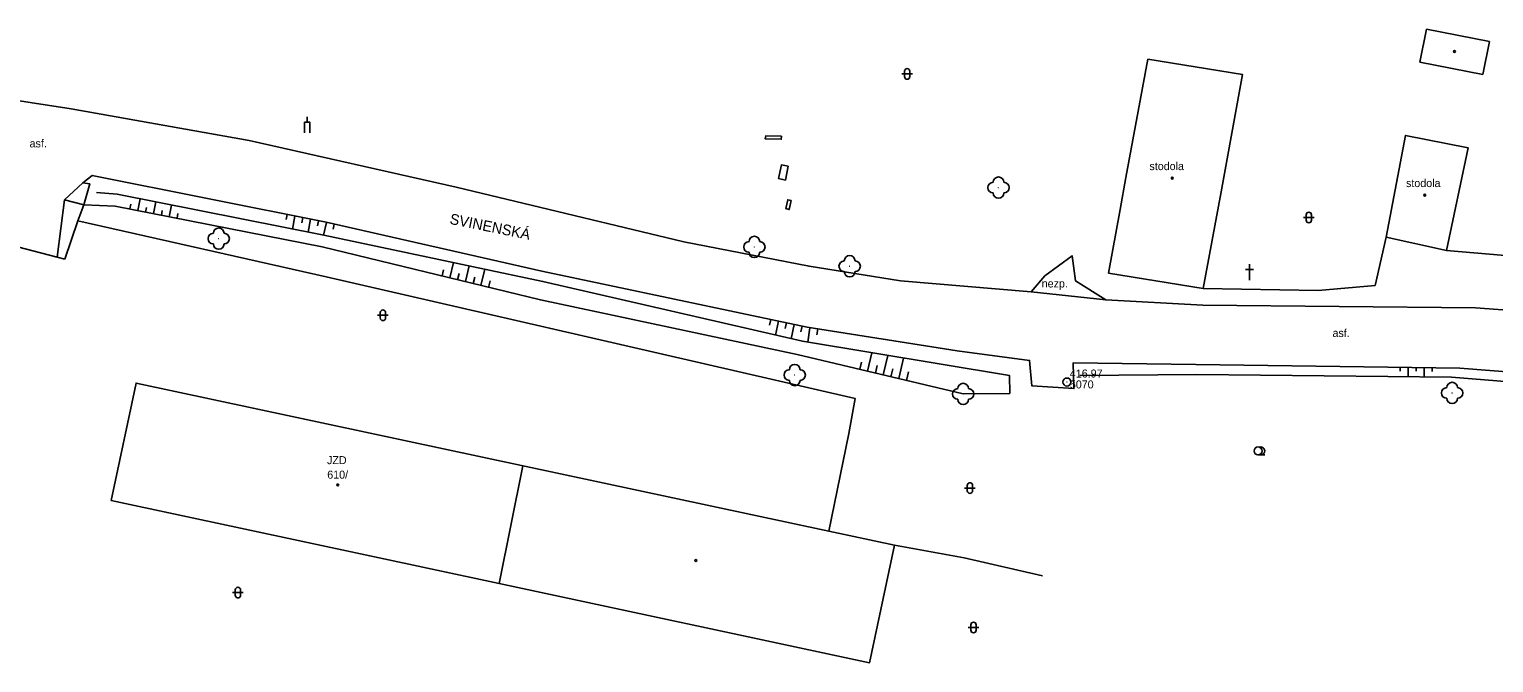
# Model space of a CAD drawing. Extents: x -737488 to -734267, y -1145775 to -1142573.
# Drawn here: x -737092.3 to -736955, y -1144940.5 to -1144881.2 of the extents above; entities that cross this region are included whole.
import ezdxf

# ---------------------------------------------------------------- set-up
doc = ezdxf.new("R2010")
doc.units = 0
for name, color, linetype in [('Vrstva 1', 7, 'Continuous'), ('Vrstva 10', 7, 'Continuous'), ('Vrstva 11', 7, 'Continuous'), ('Vrstva 12', 7, 'Continuous'), ('Vrstva 13', 7, 'Continuous'), ('Vrstva 14', 7, 'Continuous'), ('Vrstva 19', 7, 'Continuous'), ('Vrstva 3', 7, 'Continuous'), ('Vrstva 4', 7, 'Continuous'), ('Vrstva 5', 7, 'Continuous'), ('Vrstva 6', 7, 'Continuous'), ('Vrstva 8', 7, 'Continuous'), ('Vrstva 9', 7, 'Continuous')]:
    doc.layers.add(name, color=color, linetype=linetype)

# ---------------------------------------------------------------- blocks, each defined once
blk = doc.blocks.new('1.079')
at = {"layer": 'Vrstva 1'}
for radius in [0.75, 0.001]:
    blk.add_circle((0, -0.001), radius, dxfattribs=at)
blk = doc.blocks.new('3.130')
at = {"layer": 'Vrstva 1'}
blk.add_circle((0, 0), 0.001, dxfattribs=at)
for centre, start, end in [((-1, 0), 90, 270), ((0, 1), 0, 180), ((1, 0), 270, 90), ((0, -1), 180, 360)]:
    blk.add_arc(centre, 1, start, end, dxfattribs=at)
blk = doc.blocks.new('3.110')
at = {"layer": 'Vrstva 1'}
blk.add_line((0, -0.75), (1.25, -0.75), dxfattribs=at)
blk.add_circle((0, 0), 0.75, dxfattribs=at)
blk.add_arc((0.5, 0), 0.75, 249.4944, 109.0474, dxfattribs=at)
blk = doc.blocks.new('3.160')
at = {"layer": 'Vrstva 1'}
for p, q in [((-1, 0), (1, 0)), ((-0.5, -0.5), (-0.5, 0.5)), ((0.5, -0.5), (0.5, 0.5))]:
    blk.add_line(p, q, dxfattribs=at)
for centre, start, end in [((0, 0.5), 0, 180), ((0, -0.5), 180, 360)]:
    blk.add_arc(centre, 0.5, start, end, dxfattribs=at)
blk = doc.blocks.new('4.020')
at = {"layer": 'Vrstva 1'}
blk.add_circle((0, 0), 0.175, dxfattribs=at)
blk = doc.blocks.new('4.091')
at = {"layer": 'Vrstva 1'}
for p, q in [((-0.75, 0), (0.75, 0)), ((0, -2), (0, 1))]:
    blk.add_line(p, q, dxfattribs=at)
blk = doc.blocks.new('4.120')
at = {"layer": 'Vrstva 1'}
blk.add_line((0, 2), (0, 3), dxfattribs=at)
blk.add_lwpolyline([(-0.5, 0), (-0.5, 2), (0.5, 2), (0.5, 0)], dxfattribs=at)

msp = doc.modelspace()

# ---------------------------------------------------------------- linework, layer by layer
at = {"layer": 'Vrstva 10'}
for points in [[(-736998.39, -1144905.77), (-737010.64, -1144904.76), (-737019.22, -1144903.38), (-737030.95, -1144901.09), (-737052.3, -1144895.96), (-737071.69, -1144891.6), (-737088.38, -1144888.64), (-737108.04, -1144885.6), (-737134.23, -1144882.25)], [(-736876.33, -1144925.33), (-736885.57, -1144922.49), (-736933.74, -1144914.85), (-736958.22, -1144912.93), (-736982.95, -1144912.6), (-736994.45, -1144912.42), (-736994.39, -1144914.84), (-736998.35, -1144914.58), (-736998.54, -1144912.21), (-737005.32, -1144911.3), (-737019.39, -1144909.1), (-737044.26, -1144903.83), (-737064.49, -1144899.26), (-737086.4, -1144894.87), (-737087.3, -1144895.57)], [(-737089.02, -1144897.15), (-737087.3, -1144895.57)], [(-737087.21, -1144897.62), (-737086.64, -1144895.64), (-737087.3, -1144895.57)], [(-737089.68, -1144902.54), (-737089.02, -1144897.15)], [(-737089.02, -1144897.15), (-737087.21, -1144897.62)], [(-736991.4, -1144906.53), (-736994.23, -1144904.75), (-736994.56, -1144902.39), (-736997.11, -1144904.27), (-736998.39, -1144905.77)], [(-736991.4, -1144906.53), (-736998.39, -1144905.77)], [(-736873.23, -1144920.55), (-736885.29, -1144916.87), (-736912.01, -1144911.64), (-736931.7, -1144909.13), (-736956.76, -1144907.28), (-736982.3, -1144907.03), (-736991.4, -1144906.53)]]:
    msp.add_lwpolyline(points, dxfattribs=at)
at = {"layer": 'Vrstva 12'}
for points in [[(-737087.77, -1144899.12), (-737087.21, -1144897.62)], [(-737087.21, -1144897.62), (-737084.26, -1144897.74), (-737064.87, -1144901.55), (-737044.39, -1144906.54), (-737020.34, -1144911.64), (-737004.77, -1144915.35), (-737000.4, -1144915.3)], [(-737086.02, -1144896.48), (-737084.06, -1144896.63), (-737064.69, -1144900.48), (-737044.17, -1144904.8), (-737019.83, -1144910.41), (-737000.44, -1144913.62), (-737000.4, -1144915.3)], [(-737082.87, -1144898.01), (-737082.79, -1144897.57)], [(-737082.14, -1144898.16), (-737081.92, -1144897.06)], [(-737080.66, -1144898.45), (-737080.45, -1144897.35)], [(-737079.19, -1144898.74), (-737078.98, -1144897.64)], [(-737081.4, -1144898.3), (-737081.31, -1144897.86)], [(-737079.93, -1144898.59), (-737079.84, -1144898.15)], [(-737078.46, -1144898.88), (-737078.37, -1144898.44)], [(-737068.14, -1144898.53), (-737068.24, -1144899.01)], [(-737067.41, -1144898.68), (-737067.65, -1144899.89)], [(-737066.67, -1144898.82), (-737066.77, -1144899.31)], [(-737065.94, -1144898.97), (-737066.18, -1144900.18)], [(-737065.2, -1144899.12), (-737065.3, -1144899.6)], [(-737064.46, -1144899.27), (-737064.74, -1144900.47)], [(-737063.73, -1144899.43), (-737063.84, -1144899.91)], [(-737052.89, -1144904.47), (-737052.54, -1144903.04)], [(-737053.62, -1144904.29), (-737053.48, -1144903.73)], [(-737052.16, -1144904.65), (-737052.02, -1144904.07)], [(-737051.43, -1144904.82), (-737051.07, -1144903.35)], [(-737050.7, -1144905), (-737050.56, -1144904.4)], [(-737049.98, -1144905.18), (-737049.61, -1144903.66)], [(-737049.25, -1144905.36), (-737049.1, -1144904.74)], [(-737022.8, -1144908.38), (-737022.91, -1144908.89)], [(-737022.07, -1144908.53), (-737022.35, -1144909.83)], [(-737021.34, -1144908.69), (-737021.45, -1144909.21)], [(-737020.6, -1144908.84), (-737020.88, -1144910.17)], [(-737019.87, -1144909), (-737019.98, -1144909.53)], [(-737019.13, -1144909.14), (-737019.34, -1144910.49)], [(-737018.39, -1144909.26), (-737018.48, -1144909.8)], [(-737013.73, -1144913.22), (-737013.32, -1144911.49)], [(-737014.46, -1144913.04), (-737014.3, -1144912.37)], [(-737013, -1144913.39), (-737012.83, -1144912.68)], [(-737012.27, -1144913.56), (-737011.83, -1144911.73)], [(-737010.81, -1144913.91), (-737010.35, -1144911.98)], [(-736963.81, -1144912.86), (-736963.82, -1144913.2)], [(-736963.06, -1144912.87), (-736963.07, -1144913.74)], [(-736962.31, -1144912.88), (-736962.32, -1144913.22)], [(-736961.56, -1144912.89), (-736961.57, -1144913.75)], [(-736960.81, -1144912.9), (-736960.82, -1144913.24)], [(-737011.54, -1144913.74), (-737011.36, -1144912.99)], [(-737010.08, -1144914.09), (-737009.89, -1144913.29)], [(-736877.09, -1144926.5), (-736886.61, -1144923.95), (-736933.49, -1144915.84), (-736959.01, -1144913.78), (-736982.86, -1144913.52), (-736993.82, -1144913.63)]]:
    msp.add_lwpolyline(points, dxfattribs=at)
at = {"layer": 'Vrstva 4'}
for points in [[(-736982.26, -1144905.45), (-736991.14, -1144904.02), (-736990.06, -1144898.05), (-736989.52, -1144895.05), (-736987.46, -1144883.98)], [(-736959.47, -1144901.9), (-736965.12, -1144900.66)], [(-737084.63, -1144925.35), (-737082.3, -1144914.33), (-737017.37, -1144928.21)], [(-737011.2, -1144929.53), (-737017.37, -1144928.21)]]:
    msp.add_lwpolyline(points, dxfattribs=at)
at = {"layer": 'Vrstva 5'}
for points in [[(-736961.95, -1144884.26), (-736961.35, -1144881.17)], [(-736961.35, -1144881.17), (-736955.45, -1144882.32)], [(-736955.45, -1144882.32), (-736956.05, -1144885.41)], [(-736982.26, -1144905.45), (-736980.6, -1144896.41), (-736978.58, -1144885.41), (-736987.46, -1144883.98)], [(-736956.05, -1144885.41), (-736961.95, -1144884.26)], [(-736959.47, -1144901.9), (-736957.45, -1144892.28), (-736963.32, -1144891.11), (-736965.12, -1144900.66)], [(-737048.27, -1144933.12), (-737046.04, -1144922.08)], [(-737084.63, -1144925.35), (-737048.27, -1144933.12), (-737013.55, -1144940.54), (-737011.2, -1144929.53)]]:
    msp.add_lwpolyline(points, dxfattribs=at)
at = {"layer": 'Vrstva 9'}
for points in [[(-736959.47, -1144901.9), (-736932.34, -1144904.23), (-736912.38, -1144905.85), (-736906.56, -1144897.76), (-736910.1, -1144894.42), (-736915.93, -1144890.44)], [(-737021.79, -1144891.19), (-737021.83, -1144891.47), (-737023.32, -1144891.44), (-737023.28, -1144891.16), (-737021.79, -1144891.19)], [(-737021.17, -1144894.01), (-737021.8, -1144893.88), (-737022.07, -1144895.17), (-737021.44, -1144895.3), (-737021.17, -1144894.01)], [(-737020.89, -1144897.21), (-737021.08, -1144898.07), (-737021.39, -1144897.97), (-737021.21, -1144897.14), (-737020.89, -1144897.21)], [(-737087.77, -1144899.12), (-737088.98, -1144902.72)], [(-737017.37, -1144928.21), (-737015.5, -1144919.05), (-737014.88, -1144915.79), (-737043.96, -1144909.1), (-737064.48, -1144904.38), (-737087.77, -1144899.12)], [(-737094.14, -1144901.36), (-737089.68, -1144902.54)], [(-736966.15, -1144905.17), (-736965.12, -1144900.66)], [(-737089.68, -1144902.54), (-737088.98, -1144902.72)], [(-736982.26, -1144905.45), (-736971.48, -1144905.64)], [(-736966.15, -1144905.17), (-736971.48, -1144905.64)], [(-737004.69, -1144930.71), (-737011.2, -1144929.53)], [(-736997.32, -1144932.4), (-737004.69, -1144930.71)]]:
    msp.add_lwpolyline(points, dxfattribs=at)

# ---------------------------------------------------------------- block references
at = {"layer": 'Vrstva 1', "xscale": 0.5, "yscale": 0.5}
msp.add_blockref('1.079', (-736995.05, -1144914.23), dxfattribs=at)
at = {"layer": 'Vrstva 11', "xscale": 0.5, "yscale": 0.5}
for p in [(-737001.46, -1144896.01), (-737074.55, -1144900.79), (-737024.34, -1144901.57), (-737015.41, -1144903.38), (-737020.56, -1144913.58), (-736958.94, -1144915.26), (-737004.77, -1144915.35)]:
    msp.add_blockref('3.130', p, dxfattribs=at)
at = {"layer": 'Vrstva 3', "xscale": 0.5, "yscale": 0.5}
for name, p in [('3.160', (-737010.02, -1144885.35)), ('3.160', (-736972.37, -1144898.81)), ('3.160', (-737059.16, -1144907.98)), ('3.110', (-736977.13, -1144920.69)), ('3.160', (-737004.14, -1144924.17)), ('3.160', (-737072.75, -1144933.97)), ('3.160', (-737003.8, -1144937.24))]:
    msp.add_blockref(name, p, dxfattribs=at)
at = {"layer": 'Vrstva 8', "xscale": 0.5, "yscale": 0.5}
for name, p in [('4.020', (-736958.72, -1144883.25)), ('4.020', (-736985.17, -1144895.12)), ('4.020', (-736961.51, -1144896.72)), ('4.091', (-736977.93, -1144903.67)), ('4.020', (-737063.4, -1144923.88)), ('4.020', (-737029.83, -1144930.96))]:
    msp.add_blockref(name, p, dxfattribs=at)
at = {"layer": 'Vrstva 9', "xscale": 0.5, "yscale": 0.5}
msp.add_blockref('4.120', (-737066.25, -1144890.88), dxfattribs=at)

# ---------------------------------------------------------------- texts
at = {"layer": 'Vrstva 13'}
msp.add_text('SVINENSKÁ', height=1, rotation=348.643, dxfattribs=at).set_placement((-737052.96, -1144899.4))
at = {"layer": 'Vrstva 14'}
for s, p in [('asf.', (-737092.28, -1144892.24)), ('stodola', (-736987.31, -1144894.37)), ('stodola', (-736963.26, -1144895.96)), ('nezp.', (-736997.41, -1144905.37)), ('asf.', (-736970.15, -1144910.01)), ('JZD', (-737064.4, -1144921.93))]:
    msp.add_text(s, height=0.75, dxfattribs=at).set_placement(p)
at = {"layer": 'Vrstva 19'}
for s, p in [(' 416.97', (-736995.05, -1144913.81)), (' 5070', (-736995.05, -1144914.83))]:
    msp.add_text(s, height=0.75, dxfattribs=at).set_placement(p)
at = {"layer": 'Vrstva 6'}
msp.add_text('610/', height=0.75, dxfattribs=at).set_placement((-737064.38, -1144923.29))

doc.saveas('drawing.dxf')
